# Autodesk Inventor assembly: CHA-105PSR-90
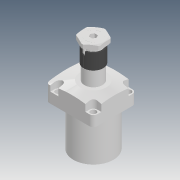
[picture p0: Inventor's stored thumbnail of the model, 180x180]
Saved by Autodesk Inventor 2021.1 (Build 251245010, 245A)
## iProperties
Created: 2018-11
Part Number: CHA-105PSR-90
Description: STEP AP214
Document SubType Name: Assembly
Designer: user
Title: CHA-105PSR-90.STEP
Revision Number: ÈÎºÎ
Sending System: SolidWorks 2016
Preprocessor: SwSTEP 2.0
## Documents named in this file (7)
- D:\Vault_2016\Projekty\Clamptek\Hydraulic\CHA-P\Inventor\CHA-105PSR-90\CHA-105PSR-90.iam
- D:\Vault_2016\Projekty\Clamptek\Hydraulic\CHA-P\Inventor\CHA-105PSR-90\CHA-105PSR-90(BT).ipt
- D:\Vault_2016\Projekty\Clamptek\Hydraulic\CHA-P\Inventor\CHA-105PSR-90\G3-8¶ÂÍ·.ipt
- D:\Vault_2016\Projekty\Clamptek\Hydraulic\CHA-P\Inventor\CHA-105PSR-90\CHA-105PS(LM).ipt
- D:\Vault_2016\Projekty\Clamptek\Hydraulic\CHA-P\Inventor\CHA-105PSR-90\CHA-105PS(HSG).ipt
- D:\Vault_2016\Projekty\Clamptek\Hydraulic\CHA-P\Inventor\CHA-105PSR-90\CHA-105PS(ZH).ipt
- D:\Vault_2016\Projekty\Clamptek\Hydraulic\CHA-P\Inventor\CHA-105PSR-90\CHA-105PS(XIAO).ipt
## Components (7 placed, 7 different names)
1. CHA-105PSR-90(BT)_1
2. G3-8¶ÂÍ·_2
3. G3-8¶ÂÍ·_3
4. CHA-105PS(LM)_4
5. CHA-105PS(HSG)_5
6. CHA-105PS(ZH)_6
7. CHA-105PS(XIAO)_7
